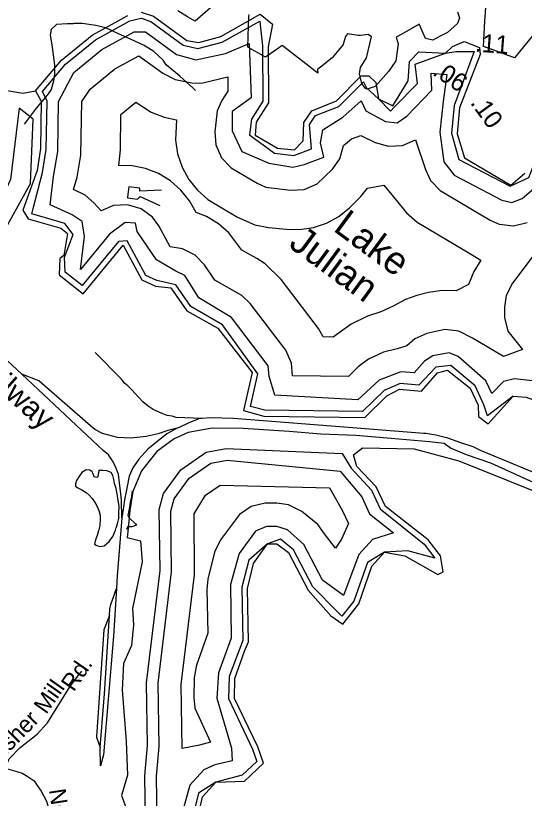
# Model space of a CAD drawing. Extents: x 945666 to 965748, y 644452 to 663300.
# Drawn here: x 952548 to 953003, y 658594 to 659294 of the extents above; entities that cross this region are included whole.
import ezdxf

# ---------------------------------------------------------------- set-up
doc = ezdxf.new("R2010")
doc.units = 0
for name, color, linetype in [('Exist Boundary Political City Limit New', 7, 'Continuous'), ('Exist Hydrographic Buffer Line', 7, 'Continuous'), ('Exist Hydrographic Creek Single Shore', 7, 'Continuous'), ('Exist Hydrographic Lake Shore', 7, 'Continuous'), ('Exist Hydrographic Lake Shore Label', 7, 'Continuous'), ('Exist Hydrographic Misc Water Feature', 7, 'Continuous'), ('Exist Hydrographic Pond Under 1500 Sq Ft', 7, 'Continuous'), ('Exist Railroad Mainline Label', 7, 'Continuous'), ('Exist Railroad Siding', 7, 'Continuous'), ('Exist Road Secondary Mileage Tenths English Label', 7, 'Continuous'), ('Exist Road Secondary Type 51 Attributed', 7, 'Continuous'), ('Exist Road Secondary Type 51 Label', 7, 'Continuous'), ('Old_Level_49', 7, 'Continuous'), ('Sheet Sticker Preliminary CELL', 7, 'Continuous'), ('Sheet Title CELL', 7, 'Continuous')]:
    doc.layers.add(name, color=color, linetype=linetype)

msp = doc.modelspace()

# ---------------------------------------------------------------- linework, layer by layer
at = {"layer": 'Exist Boundary Political City Limit New'}
for points in [[(952724.58, 659302.94), (952708.78, 659289.15), (952701.88, 659293.18), (952693.47, 659298.34)], [(953024.08, 659292.44), (952994.44, 659256.47), (952976.1, 659263.21), (952966.71, 659266.67), (952968.09, 659289.1), (952968.84, 659301.26)], [(952866.66, 659275.15), (952863.56, 659277.22), (952856.7, 659276.47), (952854.57, 659276.23), (952845.19, 659277.95), (952843.26, 659275.56), (952841.53, 659269.59), (952841.24, 659268.39), (952835.78, 659261.83), (952831.39, 659256.53), (952827.12, 659253.05), (952826.68, 659252.65), (952821, 659248.15), (952818.39, 659246.05), (952818.65, 659242.8), (952787.85, 659266.54), (952786.75, 659267.36), (952783.54, 659265.1), (952771.9, 659256.91), (952755.85, 659266.05), (952756.65, 659284.92), (952757.01, 659293.23), (952757.25, 659295.16)], [(952943.51, 659297.45), (952945.4, 659292.12), (952943.41, 659287.07), (952940.51, 659284.42), (952934.66, 659279.09), (952927.97, 659275.67), (952921.47, 659272.35), (952914.9, 659273.84), (952910.66, 659283.24), (952909.24, 659286.39), (952893.63, 659277.57), (952888.81, 659274.84), (952890.35, 659269), (952888.3, 659253.68), (952881.91, 659244.14), (952869.92, 659230.83), (952862.64, 659228.41), (952861.24, 659229.09), (952857.92, 659233.34), (952855.88, 659242.04), (952856.83, 659247.84), (952862.02, 659256.38), (952866.66, 659275.15)]]:
    msp.add_lwpolyline(points, dxfattribs=at)
at = {"layer": 'Exist Hydrographic Buffer Line'}
for p, q in [((952944.76, 659165.48), (952990.73, 659141.56)), ((952591.84, 659078.08), (952599.68, 659098.37)), ((952988.67, 659011.89), (953001.6, 658995.47)), ((952785.15, 658825.86), (952773.65, 658821.7))]:
    msp.add_line(p, q, dxfattribs=at)
for points in [[(952599.68, 659098.37), (952592.18, 659108.1), (952562.71, 659116.77), (952564, 659121.75), (952572.28, 659153.78), (952575.68, 659174.36), (952576.34, 659217.65), (952572.36, 659226.36), (952592.87, 659250.67), (952619.6, 659272.48), (952650.45, 659289.37), (952660.46, 659291.9), (952669.21, 659289.02), (952698.26, 659267.75), (952711.33, 659264.88), (952733.13, 659270.43), (952766.58, 659289.28), (952767.3, 659283.15), (952769.2, 659267.28), (952769.34, 659217.67), (952759.15, 659201.62), (952757.41, 659187.63), (952779.87, 659171.17), (952797.27, 659168.93), (952813.02, 659174.9), (952811.19, 659196.78), (952816.57, 659204.84), (952837.25, 659212.99), (952859.45, 659235.04), (952862.16, 659229.7), (952872.76, 659219.7), (952883.51, 659208.77), (952886.96, 659212.28), (952907.85, 659233.58), (952905.7, 659250.85), (952932.87, 659260.57), (952941.95, 659262.2), (952958.31, 659262.04), (952940.43, 659213.67), (952938.19, 659188.94), (952944.76, 659165.48)], [(953010.51, 658967.51), (952994.61, 658969.37), (952984.75, 658966.82), (952974.35, 658956.05), (952968.86, 658967.62), (952944.15, 658989.3), (952936.19, 658992.59), (952921.59, 658989.79), (952913.92, 658985.02), (952904.71, 658974.53), (952892.99, 658975.46), (952873.35, 658968.15), (952854.44, 658950.49), (952780.27, 658954.61), (952775, 658971.41), (952774.08, 658981.06), (952741.48, 659024.05), (952712.09, 659041.85), (952699.61, 659061.68), (952691.61, 659065.49), (952674.4, 659075.86), (952656.93, 659100.98), (952655.39, 659108.57), (952646.31, 659109.15), (952632.37, 659098.77), (952606.25, 659067.15), (952609.95, 659096.71), (952607.64, 659110.14), (952598.96, 659115.98), (952579.2, 659124.99), (952582.05, 659150.22), (952585.94, 659172.72), (952586.74, 659217.49), (952600.19, 659243.22), (952625.42, 659263.82), (952654.28, 659279.62), (952664.4, 659279.66), (952692.12, 659259.36), (952709.51, 659254.65), (952735.93, 659260.42), (952757.13, 659269.08), (952758.93, 659220.68), (952742.01, 659208.52), (952742.09, 659191.12), (952750.54, 659172.65), (952774.66, 659162.19), (952796.21, 659158.59), (952806.43, 659161.11), (952823.86, 659167.53), (952821.05, 659180.37), (952823.12, 659191.86), (952841.06, 659203.32), (952857.26, 659217.94), (952861.47, 659208.95), (952879.01, 659199.4), (952889.43, 659198.3), (952898.3, 659204.21), (952920.62, 659227.36), (952920.07, 659242.72), (952934.13, 659241.53), (952930.74, 659217.43), (952927.84, 659189.78), (952931.45, 659163.29), (952940.46, 659151.55), (952983.33, 659129.14), (952992.2, 659127.03), (953001.27, 659130.67), (953013.94, 659141.36)], [(953001.6, 658995.47), (952984.83, 658989.18), (952957.08, 659005.57), (952944.72, 659011.99), (952932.17, 659013.4), (952916.21, 659009.86), (952905.51, 659005.03), (952898.3, 658998.73), (952889.48, 658996.22), (952877.2, 658993.25), (952864.06, 658986.75), (952854.69, 658980.03), (952845.99, 658971.39), (952795.97, 658972.04), (952795.14, 658983.37), (952790.1, 658994.95), (952757.93, 659036.76), (952750.73, 659043.8), (952726.45, 659057.65), (952717.18, 659071.14), (952708.79, 659079.81), (952697.48, 659085.43), (952686.53, 659087.22), (952676.43, 659106.04), (952670.73, 659113.92), (952660.57, 659121.42), (952648.44, 659124.99), (952635.84, 659124.19), (952624.77, 659119.42), (952618.31, 659126.74), (952610.37, 659133.44), (952599.97, 659138.71), (952603.32, 659149.81), (952606.46, 659169.44), (952607.52, 659217.2), (952614.83, 659228.34), (952637.08, 659246.51), (952658.5, 659258.22), (952679.83, 659242.59), (952691.05, 659237.04), (952705.87, 659234.18), (952714.51, 659233.7), (952738.06, 659239.44), (952738.12, 659226.66), (952732.83, 659218.32), (952728.65, 659209.11), (952726.33, 659190.17), (952727.24, 659178.65), (952732.29, 659167.08), (952741, 659157.93), (952764.24, 659144.2), (952772.2, 659140.78), (952794.09, 659137.92), (952806.35, 659138.74), (952817.93, 659143.8), (952831.71, 659156.84), (952838.14, 659165.93), (952841.7, 659178.06), (952848.68, 659183.99), (952857.01, 659186.92), (952870.01, 659180.67), (952881.71, 659177.31), (952894.31, 659178.1), (952905.88, 659183.16), (952914.86, 659156.65), (952919.44, 659146.82), (952928.16, 659137.67), (952972.81, 659111.22), (952980.95, 659107.69), (952993.5, 659106.29), (953005.78, 659109.25)], [(952953.49, 659053.59), (952942.43, 659048.1), (952929.97, 659048.41), (952917.66, 659046.54), (952907.12, 659043.74), (952897.04, 659040.21), (952886.11, 659034.26), (952874.97, 659029.36), (952863.16, 659025.4), (952848.4, 659018.13), (952832.38, 659006.65), (952823.45, 659006.76), (952819.31, 659014.35), (952785.69, 659058.2), (952771.55, 659072.03), (952763.88, 659076.96), (952750.7, 659084.29), (952738.95, 659099.8), (952729.61, 659108.04), (952718.97, 659114.53), (952709.74, 659118.15), (952703.91, 659128.37), (952696.14, 659138.1), (952686.79, 659146.34), (952676.16, 659152.84), (952664.57, 659157.38), (952652.37, 659159.84), (952640.49, 659160.14), (952641.98, 659174.16), (952642.43, 659205.61), (952655.93, 659216.62), (952669.55, 659207.94), (952681.15, 659203.4), (952692.04, 659201.02), (952691.29, 659182.73), (952693.14, 659170.41), (952697.11, 659158.61), (952703.07, 659147.68), (952710.84, 659137.94), (952720.18, 659129.7), (952746.64, 659113.86), (952762.3, 659107.13), (952774.5, 659104.67), (952790.52, 659103.03), (952802.28, 659102.79), (952814.59, 659104.66), (952826.4, 659108.62), (952837.33, 659114.58), (952847.07, 659122.35), (952856.93, 659132.46), (952863.05, 659139.71), (952877.78, 659142.45), (952890.23, 659127.42), (952897.99, 659117.69), (952907.34, 659109.44), (952955.04, 659080.98), (952964.35, 659075.56), (952958.04, 659065.19), (952953.49, 659053.59)], [(952990.73, 659141.56), (953007.24, 659149.31), (953011.18, 659159.17), (953029.05, 659177.02), (953045.75, 659178.8), (953064.71, 659176.5)], [(952993.38, 658953.83), (952970.34, 658936.17), (952967.19, 658945.91), (952959.47, 658963.16), (952937.68, 658981.17), (952924.29, 658979.75), (952909.08, 658963.75), (952892.17, 658965.1), (952877.99, 658958.85), (952858.66, 658940.04), (952771.15, 658941.19), (952758.34, 658944.62), (952764.86, 658973.68), (952733.25, 659017.7), (952704.91, 659033.95), (952691.48, 659053.48), (952674.68, 659057.18), (952664.85, 659061.7), (952648.02, 659092.59), (952640.38, 659092.15), (952607.77, 659052.67)], [(952607.77, 659052.67), (952592.61, 659064.72), (952591.84, 659078.08)], [(953013.04, 659081.79), (952992.66, 659054.87), (952987.14, 659043.69), (952985.66, 659033.53), (952985.71, 659024.17)], [(952985.71, 659024.17), (952988.67, 659011.89)], [(952664.83, 658552.28), (952663.92, 658614.19), (952666.19, 658641.2), (952665.21, 658697.51), (952677.47, 658797.91), (952676.58, 658852.38), (952680.51, 658866.71), (952696.06, 658887.92), (952718.81, 658903.56), (952736.72, 658907), (952840.32, 658902.37), (952848.53, 658889.52), (952866.54, 658869.77), (952874.34, 658852.97), (952913.67, 658821.47), (952923.33, 658808.77), (952899.13, 658815.59), (952878.37, 658814.3), (952863.05, 658805.08), (952850.78, 658770.51), (952840.01, 658756.94), (952835.98, 658761.06), (952814.24, 658783.33), (952796.88, 658816.25), (952785.15, 658825.86)], [(952675.15, 658551.08), (952674.32, 658613.83), (952676.55, 658640.32), (952675.62, 658696.97), (952687.77, 658796.66), (952686.99, 658851.07), (952690.03, 658862.11), (952703.4, 658880.36), (952722.9, 658893.77), (952737.49, 658896.57), (952838.51, 658886.72), (952857.85, 658863.83), (952864.91, 658848.6), (952886.23, 658831.42)], [(952834.24, 658862.8), (952840.44, 658851.97), (952846.06, 658839.85), (952839.91, 658825.98), (952834.33, 658817.79), (952824.45, 658830.79), (952818.62, 658838.9), (952804.16, 658850.57), (952792.26, 658856.63), (952781.83, 658858.11), (952771.38, 658858), (952759.1, 658855.04), (952748.56, 658848.05), (952731.41, 658825.19), (952726.1, 658814.29), (952720.31, 658790.09), (952719.35, 658780.97), (952720.15, 658741.82), (952709.95, 658713.12), (952707.97, 658702.1), (952707.53, 658684.15), (952708.55, 658674.73), (952722.45, 658644.33), (952712.74, 658641.74), (952697.26, 658638.58), (952696.42, 658695.9), (952708.41, 658794.14), (952707.83, 658848.44), (952718.07, 658865.23), (952731.1, 658874.18), (952829.04, 658871.89), (952834.24, 658862.8)], [(952886.23, 658831.42), (952867.62, 658825.59), (952855.33, 658812.05), (952841.52, 658775.57), (952822.85, 658789.26), (952806.07, 658821.1), (952791.48, 658834.1), (952781.91, 658837.33), (952772.68, 658837.26), (952762.9, 658832.99), (952748.31, 658813.08), (952740.54, 658785.31), (952741.02, 658737.47), (952729.6, 658706.33), (952728.32, 658683.65), (952741.32, 658638.85), (952741.93, 658627.7), (952726.6, 658623.98), (952716.54, 658619.7), (952703.98, 658605.81), (952692.26, 658562.53)], [(952773.65, 658821.7), (952756.76, 658807.04), (952750.66, 658782.92), (952751.46, 658735.3), (952739.42, 658702.93), (952738.71, 658683.4), (952760.16, 658638.21), (952763.97, 658627.07), (952750.89, 658614.68), (952727.29, 658608.41), (952711.7, 658598.86), (952702.4, 658560.26), (952694.06, 658501.49), (952688.27, 658495.53), (952661.76, 658474.64), (952649.47, 658469.33)]]:
    msp.add_lwpolyline(points, dxfattribs=at)
at = {"layer": 'Exist Hydrographic Creek Single Shore'}
msp.add_lwpolyline([(952332.6, 659363.1), (952363.43, 659340.89), (952391.12, 659328.73), (952405.78, 659315.85), (952420.09, 659297.31), (952437.78, 659284.79), (952459.62, 659287.9), (952535.2, 659228.17), (952554.77, 659224.95), (952566.09, 659226.99)], dxfattribs=at)
at = {"layer": 'Exist Hydrographic Lake Shore'}
for points in [[(952566.09, 659226.99), (952589.2, 659254.38), (952616.68, 659276.81), (952648.54, 659294.25)], [(952660.64, 659297.31), (952671.62, 659293.7), (952701.33, 659271.94), (952712.24, 659269.99), (952731.73, 659275.44), (952767.1, 659295.56), (952777.99, 659286.65), (952774.31, 659266.36), (952774.54, 659216.18), (952763.54, 659198.84), (952762.59, 659187.2), (952782.48, 659175.67), (952797.81, 659174.1), (952805.56, 659182.12), (952806.04, 659198.42), (952813.15, 659209.08), (952835.34, 659217.83), (952857.25, 659240.23), (952864.2, 659240.25), (952870.52, 659234.32), (952872.76, 659219.7), (952885.76, 659213.45), (952899.38, 659235.79), (952900.65, 659253.09), (952908.93, 659261.77), (952932.87, 659260.57), (952939.02, 659266.6), (952949.41, 659270.97), (952963.22, 659265.73), (952963.74, 659259.41), (952945.27, 659211.79), (952943.38, 659188.51), (952949.74, 659166.95), (952991.22, 659142.59), (953003.89, 659153.28)], [(952566.09, 659226.99), (952571.15, 659217.72), (952570.54, 659175.18), (952567.4, 659155.55), (952554.56, 659120.27), (952559.32, 659112.31), (952588.79, 659104.17), (952594.55, 659099.2), (952591.39, 659079.58), (952587.88, 659076.91), (952587.32, 659062.28), (952608.52, 659045.44), (952644.39, 659088.84), (952661.09, 659057.7), (952673.27, 659052.11), (952687.2, 659050.54), (952701.32, 659030.01), (952729.14, 659014.53), (952759.8, 658974.82), (952752.18, 658940.89), (952770.43, 658936), (952860.77, 658934.82)], [(952860.77, 658934.82), (952880.31, 658954.21), (952891.76, 658959.92), (952911.26, 658958.37), (952925.64, 658974.74), (952934.45, 658977.1), (952954.78, 658960.93), (952962.01, 658945.69), (952962.4, 658935.71), (952970.97, 658929.12), (952993.38, 658953.83), (953005.08, 658952.9), (953025.37, 658945.36), (953052.15, 658919.93), (953051.66, 658896.65), (953069.49, 658887.78), (953058.67, 658857.09)], [(952751.81, 658924.83), (952724.14, 658925.3), (952702.48, 658921.34), (952690.17, 658915.77), (952674.7, 658904.32), (952660.78, 658887.04), (952653.1, 658868.67), (952650.31, 658851.39), (952648.56, 658832.74), (952648.04, 658827.27)], [(953058.67, 658857.09), (953031.16, 658868.01), (953006.17, 658878.95), (952973.41, 658893.74), (952951.46, 658901.19), (952937.25, 658907.3), (952931.6, 658911.47), (952918.43, 658913.07), (952884.26, 658915.8), (952852.6, 658918.55), (952821.15, 658919.89), (952792.81, 658922.06), (952751.81, 658924.83)], [(952707.48, 658559.13), (952715.56, 658595.38), (952727.29, 658608.41), (952753.07, 658609.57), (952769.97, 658625.6), (952764.97, 658640.2), (952743.9, 658683.28), (952744.33, 658701.23), (952752.85, 658725.86), (952756.69, 658734.21), (952755.71, 658781.72), (952760.98, 658804.01), (952773.65, 658821.7), (952781.98, 658821.74), (952792.28, 658813.82), (952809.93, 658780.36), (952830.27, 658757.2), (952841.09, 658749.95), (952855.4, 658767.98), (952866.91, 658801.6), (952878.37, 658814.3), (952896.56, 658811.07), (952926.09, 658794.27), (952930.73, 658796.63), (952928.23, 658810.91), (952917.4, 658825.15), (952879.06, 658855.17), (952870.9, 658872.74), (952853.53, 658890.92), (952850.65, 658901.2)], [(952850.65, 658901.2), (952858.46, 658907.57), (952904.88, 658906.83), (952944.73, 658896.08), (953077.86, 658842.63)], [(952648.04, 658827.27), (952659.95, 658824.35), (952661.41, 658805.69), (952652.87, 658763.92), (952653.73, 658749.22), (952651.8, 658730.71), (952644.76, 658714.81), (952643.62, 658691.03), (952647.18, 658645.03), (952648.36, 658614.85), (952643.03, 658596.51), (952648.81, 658580.52), (952644.94, 658543.52), (952634.45, 658510.23), (952623.52, 658484.29), (952622.13, 658473.08)]]:
    msp.add_lwpolyline(points, dxfattribs=at)
at = {"layer": 'Exist Hydrographic Misc Water Feature'}
for points in [[(952709.09, 659227.23), (952707, 659229.28), (952695.16, 659239.88), (952683.01, 659250.29), (952680.2, 659254.4), (952671.74, 659262.19), (952663.1, 659267.54), (952654.99, 659271.42), (952639.56, 659278.12), (952635.87, 659280.09), (952628.88, 659283.32), (952619.87, 659285.3), (952607.89, 659286.98), (952600.42, 659287.14), (952599.59, 659286.91), (952594.59, 659286.89), (952584.76, 659286.28), (952580.16, 659281.84), (952579.19, 659276.8), (952580.51, 659268.04), (952582.9, 659250.07), (952582.96, 659241.85), (952582.21, 659235.54), (952580.1, 659228.13), (952576.59, 659222.88), (952566.53, 659211.46), (952556, 659197.17)], [(952678.63, 659137.96), (952659.38, 659137.07), (952659.45, 659139.81), (952649.61, 659141.14), (952648.65, 659134.56)], [(952648.65, 659134.56), (952648.37, 659131.13), (952657.39, 659129.99), (952659.7, 659132.52), (952677.17, 659124.47)]]:
    msp.add_lwpolyline(points, dxfattribs=at)
at = {"layer": 'Exist Hydrographic Pond Under 1500 Sq Ft'}
for points in [[(952541.15, 659107.46), (952561.6, 659143.99), (952563.9, 659201.58), (952551.33, 659211.25), (952543.67, 659147.67), (952528.48, 659115.69), (952541.15, 659107.46)], [(952640.44, 658845.52), (952640.52, 658849.11), (952640.97, 658855.44), (952640.1, 658860.61), (952639.37, 658864.63), (952638.19, 658871.13), (952636.81, 658875.63), (952635.97, 658879.29), (952635.23, 658882.86), (952633.65, 658885.57), (952629.97, 658887.13), (952626.18, 658887.45), (952622.8, 658887.26), (952621.84, 658881.54), (952620.51, 658881.06), (952618.37, 658881.63), (952617.72, 658884.28), (952616.75, 658886.1), (952614.62, 658887.53), (952611.32, 658887.91), (952607.58, 658885.63), (952605.31, 658882.42), (952602.61, 658878.27), (952601.72, 658875.29), (952601.93, 658873.19), (952603.89, 658871.9), (952607.39, 658870.07), (952611.41, 658867.62), (952614.18, 658865.28), (952616.77, 658862.21), (952618.82, 658859.36), (952620.82, 658855.66), (952622.68, 658851.65), (952623.86, 658847.3), (952623.98, 658843.34), (952623.5, 658838.11), (952622.53, 658833.48), (952621.05, 658829.03), (952619.74, 658825.31), (952618.74, 658821.56), (952620.19, 658820.44), (952623.15, 658819.25), (952627.34, 658819.89), (952632.03, 658823.82), (952635.06, 658828.37), (952637.68, 658834.09), (952638.29, 658836.21)], [(952652.62, 658869.27), (952651.55, 658862.14), (952650.66, 658858.96), (952650.2, 658854.57), (952649.29, 658850.12), (952648.61, 658847.2), (952649.88, 658844.93)], [(952640.44, 658845.52), (952639.07, 658839.69), (952638.29, 658836.21)], [(952649.88, 658844.93), (952655.54, 658839.5), (952656.28, 658838.28), (952652.27, 658837.06), (952648.18, 658836.98), (952647.5, 658834.5)]]:
    msp.add_lwpolyline(points, dxfattribs=at)
at = {"layer": 'Exist Railroad Siding'}
msp.add_line((952553.83, 658973.41), (952501.65, 659021.7), dxfattribs=at)
for points in [[(952715.16, 658933.88), (952692.01, 658934.68), (952688.21, 658935.89), (952683.89, 658936.63), (952679.47, 658938.3), (952674.66, 658940.5), (952671.16, 658941.9), (952666.94, 658944.93), (952662, 658948.73), (952658.81, 658952.26), (952655.27, 658956.27), (952652.07, 658959.59), (952648.57, 658963.14), (952645.7, 658965.35), (952642.71, 658969.15), (952619.26, 658992.78)], [(952643.2, 658844.91), (952643.08, 658860.7), (952642.29, 658866.46), (952641.22, 658876.32), (952640.22, 658883.76), (952637.51, 658890.79), (952634.81, 658896.09), (952631.29, 658901.37), (952626.63, 658905.17), (952553.83, 658973.41)], [(952692.68, 658925.14), (952684.44, 658923.09), (952675.64, 658919.96), (952665.01, 658917.6), (952651.31, 658916.09), (952639.25, 658916.76), (952625.89, 658920.36), (952619.72, 658923.6), (952617.56, 658925.05), (952569, 658967.55), (952553.83, 658973.41)], [(952715.16, 658933.88), (952712.09, 658933.66), (952702.49, 658929.64), (952694.43, 658925.73), (952692.68, 658925.14)], [(953073.65, 658859.74), (952964.19, 658905.2), (952957.51, 658908.4), (952946.54, 658912.1), (952935.03, 658916.22), (952924.25, 658918.92), (952915.13, 658920.34), (952913.29, 658920.46), (952861.06, 658924.49), (952743.29, 658933.75), (952722.6, 658934.39), (952715.16, 658933.88)], [(952692.68, 658925.14), (952683.42, 658920.22), (952666.54, 658906.53), (952658.42, 658897.5), (952653.07, 658889.57), (952649.95, 658882.29), (952648, 658873.04), (952645.54, 658861.17), (952644.78, 658854.44), (952643.2, 658844.91)], [(952643.2, 658844.91), (952639.23, 658793.11), (952638.41, 658781.7)], [(952638.41, 658781.7), (952635.68, 658739.07), (952627, 658633), (952624.12, 658623.2)], [(952632.26, 658757.62), (952632.63, 658763.14), (952633.43, 658767.47), (952638.41, 658781.7)], [(952632.26, 658757.62), (952627.06, 658744.84), (952620.66, 658649.54), (952620.69, 658648.66), (952623.75, 658639.43)], [(952623.75, 658639.43), (952627.63, 658687.41), (952632.26, 658757.62)], [(952624.12, 658623.2), (952623.75, 658639.43)]]:
    msp.add_lwpolyline(points, dxfattribs=at)
at = {"layer": 'Exist Road Secondary Type 51 Attributed'}
for points in [[(952538.83, 658621.21), (952540.53, 658625.12), (952542.41, 658629.48), (952552.45, 658639.48), (952567.61, 658651.44), (952576.86, 658661.58), (952596.81, 658693.78), (952603.46, 658702.99), (952607.51, 658707.74)], [(952538.83, 658621.21), (952547.25, 658618.83), (952553.96, 658616.54), (952557.75, 658614.48), (952564.84, 658609.7), (952567.41, 658605.59), (952571.13, 658600.63), (952575.88, 658591.67), (952578.65, 658582.03), (952580.78, 658565.71), (952581.64, 658556.04), (952582.97, 658542.02), (952586.67, 658491.09), (952588.4, 658469.76), (952591.07, 658427.09), (952591.1, 658412.52), (952591.14, 658406.64), (952591.15, 658399.33), (952590.7, 658391.2), (952589.55, 658376.03), (952585.63, 658355.48), (952576.67, 658332.4)]]:
    msp.add_lwpolyline(points, dxfattribs=at)

# ---------------------------------------------------------------- texts
at = {"layer": 'Exist Hydrographic Lake Shore Label'}
for s, p in [('Lake', (952831.42, 659102.3)), ('Julian', (952791.46, 659087.87))]:
    msp.add_text(s, height=24.682, rotation=323.59084, dxfattribs=at).set_placement(p)
at = {"layer": 'Exist Railroad Mainline Label'}
msp.add_text('Railway', height=19.486, rotation=318.4103, dxfattribs=at).set_placement((952504.12, 658983.37))
at = {"layer": 'Exist Road Secondary Mileage Tenths English Label'}
msp.add_text('.10', height=16.238, rotation=305.99954, dxfattribs=at).set_placement((952954.45, 659216.07))
at = {"layer": 'Exist Road Secondary Type 51 Label'}
for s, rotation, p in [('Rd.', 55.44905, (952600.14, 658688.82)), ('Mill', 54.8905, (952575.65, 658668.56)), ('Fisher', 45.62405, (952531.31, 658623.76)), ('New', 278.57946, (952578, 658601.63))]:
    msp.add_text(s, height=15, rotation=rotation, dxfattribs=at).set_placement(p)
at = {"layer": 'Old_Level_49'}
msp.add_text('.11', height=16.238, rotation=355.66693, dxfattribs=at).set_placement((952958.81, 659262.05))
at = {"layer": 'Sheet Sticker Preliminary CELL'}
msp.add_text('.06', height=16.238, rotation=326.09073, dxfattribs=at).set_placement((952920.28, 659241.79))
at = {"layer": 'Sheet Title CELL'}
msp.add_text('TIP PROJECT:', height=249.9998, rotation=53.59084, dxfattribs=at).set_placement((951327.58, 658659.91))

doc.saveas('drawing.dxf')
